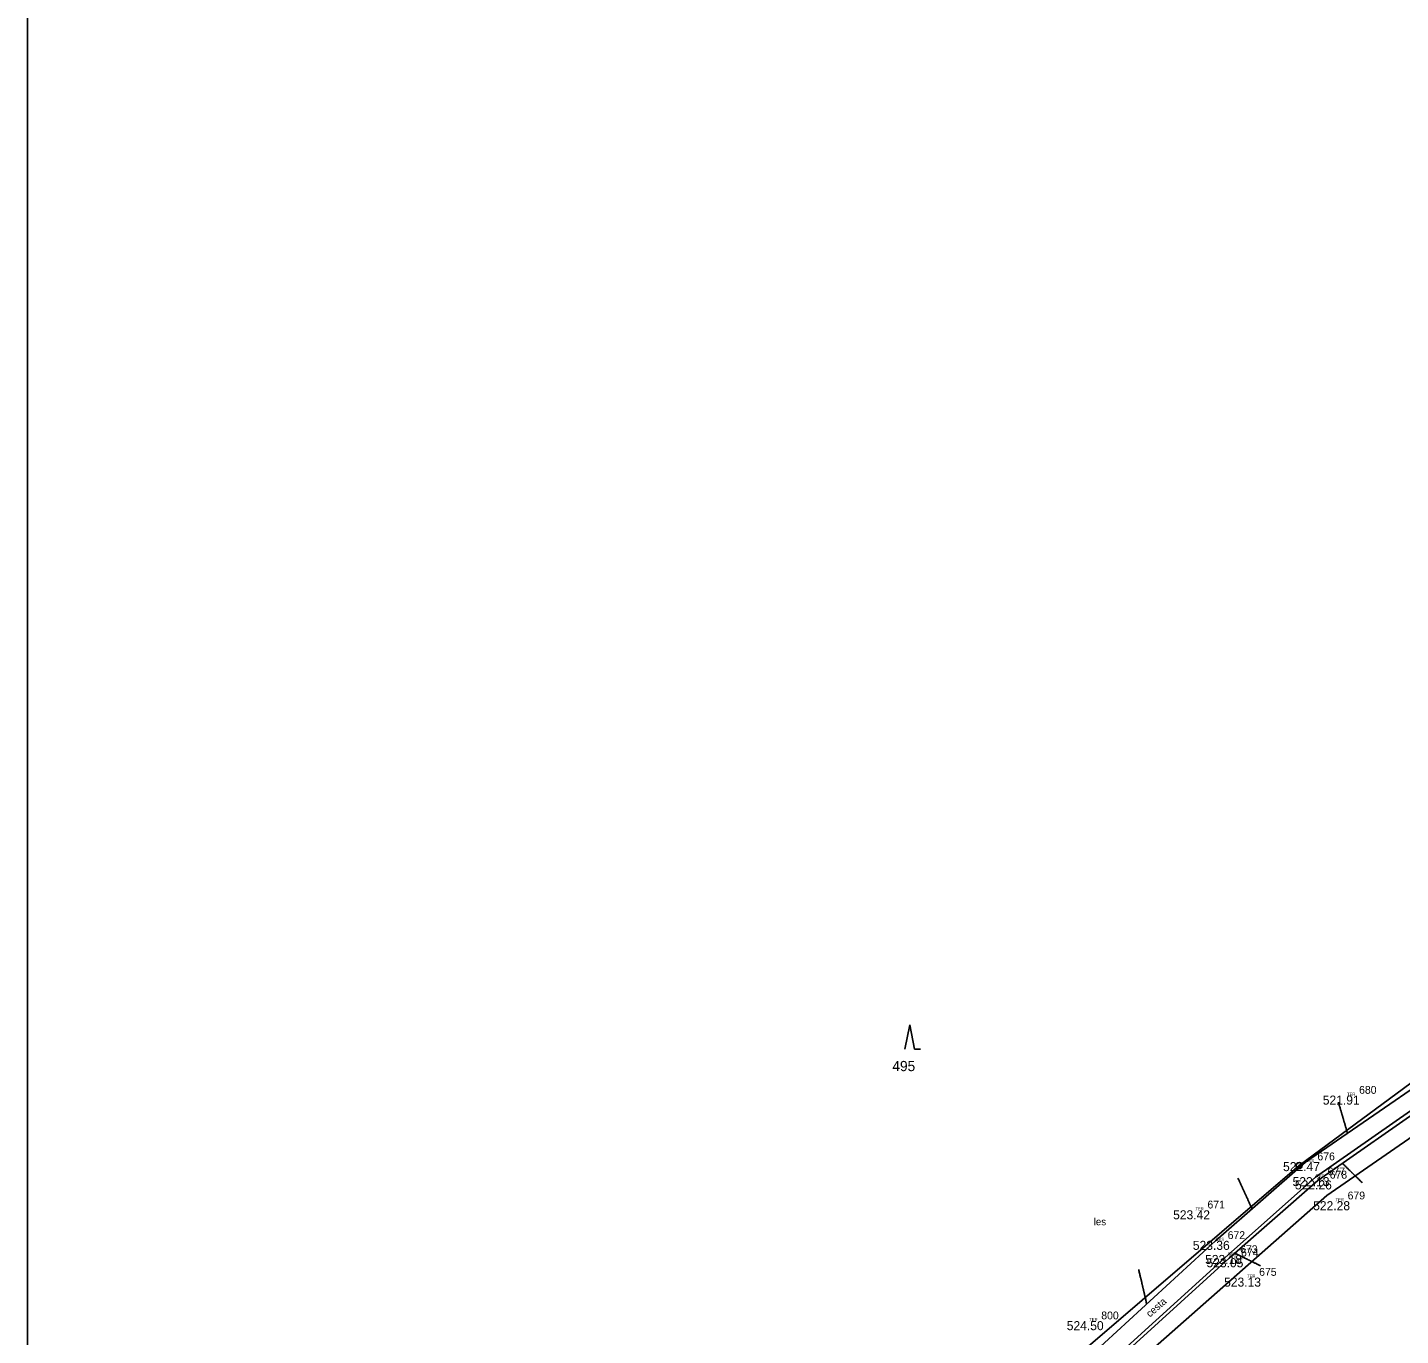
# Model space of a CAD drawing. Extents: x -604848 to -603227, y -1111879 to -1109838.
# Drawn here: x -604375.4 to -604147, y -1110966.8 to -1110749.4 of the extents above; entities that cross this region are included whole.
import ezdxf

# ---------------------------------------------------------------- set-up
doc = ezdxf.new("R2010")
doc.units = 0
for name, color, linetype in [('1', 7, 'Continuous'), ('10', 7, 'Continuous'), ('14', 7, 'Continuous'), ('18', 7, 'Continuous'), ('19', 7, 'Continuous'), ('20', 7, 'Continuous'), ('23', 7, 'Continuous'), ('28', 7, 'Continuous'), ('4', 7, 'Continuous'), ('7', 7, 'Continuous'), ('9', 7, 'Continuous'), ('Default', 7, 'Continuous')]:
    doc.layers.add(name, color=color, linetype=linetype)

# ---------------------------------------------------------------- blocks, each defined once
blk = doc.blocks.new('Z105')
at = {"layer": '28'}
for radius in [0.5, 0.01]:
    blk.add_circle((0, 0), radius, dxfattribs=at)
blk = doc.blocks.new('POINT_DISPLAY')
at = {"layer": 'Default'}
blk.add_line((0, 0), (0, 0), dxfattribs=at)
blk = doc.blocks.new('Z3080')
at = {"layer": '23'}
for p, q in [((-0.8, 0), (0, 4)), ((0, 4), (0.8, 0)), ((0.8, 0), (1.8, 0))]:
    blk.add_line(p, q, dxfattribs=at)

msp = doc.modelspace()

# ---------------------------------------------------------------- linework, layer by layer
at = {"layer": '1'}
for p, q in [((-604130.35, -1110913.8), (-604163.92, -1110938.59)), ((-604159.32, -1110943.54), (-604139.15, -1110929.61)), ((-604163.92, -1110938.59), (-604232.79, -1110997.55)), ((-604197.35, -1110977.02), (-604159.32, -1110943.54))]:
    msp.add_line(p, q, dxfattribs=at)
msp.add_lwpolyline([(-603781.41, -1111422.77), (-603781.41, -1110582.77), (-604375.41, -1110582.77), (-604375.41, -1111422.77), (-603781.41, -1111422.77)], dxfattribs=at)
at = {"layer": '10'}
for p, q in [((-604136.49, -1110924.1), (-604160.83, -1110941.04)), ((-604160.83, -1110941.04), (-604175.57, -1110953.98)), ((-604175.57, -1110953.98), (-604195.98, -1110972.55))]:
    msp.add_line(p, q, dxfattribs=at)
at = {"layer": '4'}
for p, q in [((-604162.87, -1110938), (-604138.58, -1110921.29)), ((-604136.84, -1110923.49), (-604161.18, -1110940.5)), ((-604177.8, -1110951.09), (-604162.87, -1110938)), ((-604161.18, -1110940.5), (-604175.73, -1110953.43)), ((-604198.35, -1110969.93), (-604177.8, -1110951.09)), ((-604175.73, -1110953.43), (-604196.36, -1110972.1))]:
    msp.add_line(p, q, dxfattribs=at)
at = {"layer": '7'}
for points in [[(-604155.87, -1110933.19), (-604156.37, -1110931.47), (-604156.88, -1110929.75), (-604157.39, -1110928.03)], [(-604156.74, -1110938.19), (-604155.63, -1110939.27), (-604154.52, -1110940.35), (-604153.41, -1110941.43)], [(-604171.74, -1110945.78), (-604172.52, -1110944.07), (-604173.3, -1110942.36), (-604174.09, -1110940.66)], [(-604174.61, -1110953.14), (-604173.17, -1110953.84), (-604171.74, -1110954.55), (-604170.31, -1110955.25)], [(-604189.26, -1110961.59), (-604189.7, -1110959.68), (-604190.15, -1110957.77), (-604190.6, -1110955.86)]]:
    msp.add_open_spline(points, degree=2, dxfattribs=at)

# ---------------------------------------------------------------- block references
at = {"layer": '18'}
for p in [(-604155.94, -1110926.94), (-604162.87, -1110938), (-604161.18, -1110940.5), (-604160.83, -1110941.04), (-604181.16, -1110946.01), (-604157.85, -1110944.5), (-604177.8, -1110951.09), (-604175.73, -1110953.43), (-604175.57, -1110953.98), (-604172.56, -1110957.2), (-604198.82, -1110964.44)]:
    msp.add_blockref('POINT_DISPLAY', p, dxfattribs=at)
at = {"layer": '23'}
msp.add_blockref('Z3080', (-604228.68, -1110919.2), dxfattribs=at)
at = {"layer": '28'}
msp.add_blockref('Z105', (-604163.92, -1110938.59), dxfattribs=at)

# ---------------------------------------------------------------- texts
at = {"layer": '14'}
msp.add_text('495', height=1.7, dxfattribs=at).set_placement((-604231.56, -1110922.88))
at = {"layer": '18'}
for s, p in [('TER', (-604155.94, -1110926.94)), ('CES', (-604162.87, -1110938)), ('CES', (-604161.18, -1110940.5)), ('POL', (-604160.83, -1110941.04)), ('TER', (-604181.16, -1110946.01)), ('TER', (-604157.85, -1110944.5)), ('CES', (-604177.8, -1110951.09)), ('CES', (-604175.73, -1110953.43)), ('POL', (-604175.57, -1110953.98)), ('TER', (-604172.56, -1110957.2)), ('TER', (-604198.82, -1110964.44))]:
    msp.add_text(s, height=0.5, dxfattribs=at).set_placement(p)
at = {"layer": '19'}
for s, p in [('680', (-604153.94, -1110926.64)), ('676', (-604160.87, -1110937.7)), ('677', (-604159.18, -1110940.2)), ('678', (-604158.83, -1110940.74)), ('679', (-604155.85, -1110944.2)), ('671', (-604179.16, -1110945.71)), ('672', (-604175.8, -1110950.79)), ('673', (-604173.73, -1110953.13)), ('674', (-604173.57, -1110953.68)), ('675', (-604170.56, -1110956.9)), ('800', (-604196.82, -1110964.14))]:
    msp.add_text(s, height=1.3, dxfattribs=at).set_placement(p)
at = {"layer": '20'}
for s, p in [('521.91 ', (-604159.98, -1110928.44)), ('522.47 ', (-604166.59, -1110939.5)), ('522.13 ', (-604165, -1110942)), ('522.26 ', (-604164.61, -1110942.54)), ('523.42 ', (-604184.87, -1110947.51)), ('522.28 ', (-604161.58, -1110946)), ('523.36 ', (-604181.59, -1110952.59)), ('523.18 ', (-604179.55, -1110954.93)), ('523.05 ', (-604179.32, -1110955.48)), ('523.13 ', (-604176.39, -1110958.7)), ('524.50 ', (-604202.56, -1110965.94))]:
    msp.add_text(s, height=1.5, dxfattribs=at).set_placement(p)
at = {"layer": '9'}
msp.add_text('les', height=1.2, dxfattribs=at).set_placement((-604198.07, -1110948.5))
msp.add_text('cesta', height=1.2, rotation=41.4, dxfattribs=at).set_placement((-604188.73, -1110963.87))

doc.saveas('drawing.dxf')
